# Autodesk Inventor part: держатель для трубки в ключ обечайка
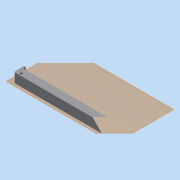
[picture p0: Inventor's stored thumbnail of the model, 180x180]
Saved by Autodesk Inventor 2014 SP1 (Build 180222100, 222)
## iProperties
Created: 2015-10
Part Number: держатель для трубки в ключ обечайка
Material: Типовые
Document SubType Name: Modeling
Designer: hals
Density: 1 g/cm^3
Appearance: По умолчанию
Author: hals
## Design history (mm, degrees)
node "РабПлоскость1"
sketch "Эскиз1"
  geometry: L1 (2, -79.959)-(148.131, -79.959); L2 (150.131, -77.959)-(150.131, -64.039); L3 (0, -64.039)-(0, -77.959); L4 (0, -79.959)-(150.131, 2.427); L5 (150.131, -79.959)-(0, 2.427); L6 (2.5, -64.039)-(2.5, -72.369); L7 (4.5, -74.369)-(145.5, -74.369); L8 (147.5, -72.369)-(147.5, -64.039); L9 (0, -64.039)-(2.5, -64.039); L10 (147.5, -64.039)-(150.131, -64.039); A1 r 2 centre (2, -77.959) between (0, -77.959) and (2, -79.959); A2 r 2 centre (148.131, -77.959) between (148.131, -79.959) and (150.131, -77.959); A3 r 2 centre (4.5, -72.369) between (2.5, -72.369) and (4.5, -74.369); A4 r 2 centre (145.5, -72.369) between (145.5, -74.369) and (147.5, -72.369); 3 further points
  constraints: 20 end point, 9 point on line, 8 point on circle, 8 tangent, 4 centre point, 3 parallel, 2 equal radius, 2 perpendicular, 1 horizontal
  dimensions: "d0" = 2 radius of A1; "d1" = 145 distance of point (2.5, -74.369) point (147.5, -74.369); "d2" = 2.5 distance between parallel lines of L6 L3; "d4" = 2 radius of A3
extrude "Выдавливание1" new body sketch "Эскиз1" distance "d5" = 13; taper "d6" = 0 deg
sketch "Эскиз2"
  geometry: L1 (2, -79.959)-(148.131, -79.959) reference; L2 (150.131, -77.959)-(150.131, -64.039) reference; L3 (150.131, -64.039)-(147.5, -64.039) reference; L4 (147.5, -64.039)-(147.5, -72.369) reference; L5 (145.5, -74.369)-(4.5, -74.369) reference; L6 (2.5, -72.369)-(2.5, -64.039) reference; L7 (2.5, -64.039)-(0, -64.039) reference; L8 (0, -64.039)-(0, -77.959) reference; L9 (2.5, -68.204)-(147.5, -68.204); A1 r 2 centre (148.131, -77.959) between (148.131, -79.959) and (150.131, -77.959) reference; A2 r 2 centre (145.5, -72.369) between (145.5, -74.369) and (147.5, -72.369) reference; A3 r 2 centre (4.5, -72.369) between (2.5, -72.369) and (4.5, -74.369) reference; A4 r 2 centre (2, -77.959) between (0, -77.959) and (2, -79.959) reference; 1 further point
  constraints: 2 end point, 2 midpoint
extrude "Выдавливание2" join sketch "Эскиз2" distance "d7" = 1.5; taper "d8" = 0 deg
fillet "Сопряжение1" dims "d9" = 2
fillet "Сопряжение2" dims "d10" = 0.5
fillet "Сопряжение3" dims "d11" = 0.5
node "Отверстие3"
node "Отверстие5"
node "Твердое тело1"
sketch "Эскиз4"
  geometry: 1 further point
hole "Отверстие2" sketch "Эскиз4" diameter "d19" = 3.4; stored, may be unused: countersink angle "d23" = 90 deg, drill point angle "d25" = 0 deg; dims "d20" = 6, "d21" = 4, "d22" = 2, "d24" = 8
sketch "Эскиз5"
  geometry: 1 further point
hole "Отверстие4" sketch "Эскиз5" diameter "d26" = 3.4; stored, may be unused: countersink angle "d30" = 90 deg, drill point angle "d32" = 0 deg; dims "d27" = 6, "d28" = 4, "d29" = 2, "d31" = 8
